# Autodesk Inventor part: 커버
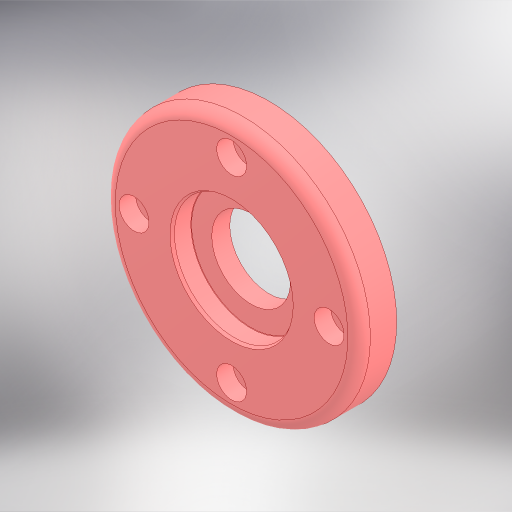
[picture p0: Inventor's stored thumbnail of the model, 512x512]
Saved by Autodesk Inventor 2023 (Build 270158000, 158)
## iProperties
Created: 2026-07
Part Number: 커버
Material: 알루미늄 6061
Document SubType Name: Modeling
Designer: home
Density: 2.71 g/cm^3
Appearance: 기본값
Author: jhkim
Sending System: Autodesk Inventor 2027
Preprocessor: ST-DEVELOPER v20.1
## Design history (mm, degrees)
feature "솔리드1"
node "솔리드2"
